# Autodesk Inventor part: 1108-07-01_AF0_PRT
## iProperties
Created: 2007-03
Part Number: 1108-07-01_AF0_PRT
Document SubType Name: Modeling
Designer: Andy Moles
Material: Steel
Mass: 17.077 g
Surface Area: 26.9271 cm^2
Volume: 2.17541 cm^3
Density: 7.85 g/cm^3
Author: Andy Moles
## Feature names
1. Base1
